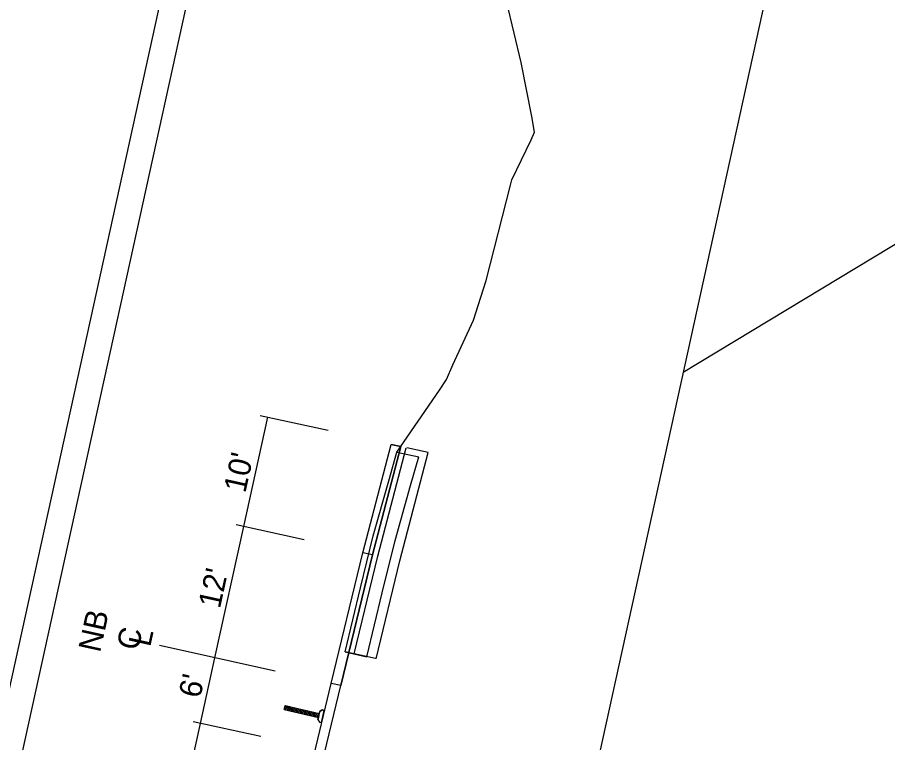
# Model space of a CAD drawing. Extents: x 14104283 to 14121738, y 8635219 to 8671666.
# Drawn here: x 14107408.8 to 14107719.8, y 8639476.7 to 8639735.9 of the extents above; entities that cross this region are included whole.
import ezdxf

# ---------------------------------------------------------------- set-up
doc = ezdxf.new("R2010")
doc.units = 0
for name, color, linetype in [('Cell', 7, 'Continuous'), ('dsnNonPlotable', 7, 'Continuous'), ('dsnShadingPaved', 7, 'Continuous'), ('dsnTextFinalPlan', 7, 'Continuous'), ('dsnTextOverlapEven', 7, 'Continuous'), ('TC_ShoulderPCC', 7, 'Continuous'), ('TC_Subbase', 7, 'Continuous'), ('TC_SubgradeTreatment', 7, 'Continuous'), ('TC_SubstrataExistingPavement', 7, 'Continuous'), ('Terrain', 7, 'Continuous')]:
    doc.layers.add(name, color=color, linetype=linetype)

msp = doc.modelspace()

# ---------------------------------------------------------------- linework, layer by layer
at = {"layer": 'Cell'}
for p, q in [((14107504.17, 8639488.53), (14107504.51, 8639489.98)), ((14107504.51, 8639489.98), (14107516.71, 8639487.11)), ((14107505.67, 8639488.18), (14107504.57, 8639489.96)), ((14107506.44, 8639488), (14107505.34, 8639489.78)), ((14107504.17, 8639488.53), (14107516.37, 8639485.66)), ((14107504.9, 8639488.36), (14107504.34, 8639489.26)), ((14107507.22, 8639487.82), (14107506.11, 8639489.6)), ((14107507.99, 8639487.63), (14107506.88, 8639489.42)), ((14107508.76, 8639487.45), (14107507.66, 8639489.24)), ((14107509.54, 8639487.27), (14107508.43, 8639489.06)), ((14107510.31, 8639487.09), (14107509.2, 8639488.87)), ((14107511.08, 8639486.91), (14107509.98, 8639488.69)), ((14107511.86, 8639486.72), (14107510.75, 8639488.51)), ((14107512.63, 8639486.54), (14107511.52, 8639488.33)), ((14107513.4, 8639486.36), (14107512.3, 8639488.15)), ((14107514.17, 8639486.18), (14107513.07, 8639487.97)), ((14107514.95, 8639486), (14107513.84, 8639487.78)), ((14107515.72, 8639485.82), (14107514.62, 8639487.6)), ((14107516.4, 8639485.79), (14107515.39, 8639487.42)), ((14107516.58, 8639486.56), (14107516.16, 8639487.24)), ((14107516.2, 8639484.94), (14107516.88, 8639487.83)), ((14107516.71, 8639487.11), (14107516.37, 8639485.66)), ((14107516.88, 8639487.83), (14107516.71, 8639487.11)), ((14107517.76, 8639488.39), (14107516.88, 8639487.83)), ((14107516.88, 8639487.83), (14107517.76, 8639488.39)), ((14107517.46, 8639483.88), (14107518.48, 8639488.22)), ((14107517.46, 8639483.88), (14107518.48, 8639488.22)), ((14107518.48, 8639488.22), (14107517.76, 8639488.39)), ((14107517.76, 8639488.39), (14107518.48, 8639488.22)), ((14107516.37, 8639485.66), (14107516.2, 8639484.94)), ((14107516.2, 8639484.94), (14107516.74, 8639484.05)), ((14107516.2, 8639484.94), (14107516.74, 8639484.05)), ((14107516.74, 8639484.05), (14107517.46, 8639483.88)), ((14107516.74, 8639484.05), (14107517.46, 8639483.88))]:
    msp.add_line(p, q, dxfattribs=at)
at = {"layer": 'dsnNonPlotable'}
msp.add_lwpolyline([(14107218.44, 8638642.33), (14107554.83, 8640173.31), (14108541.3, 8639956.56), (14108204.91, 8638425.58)], close=True, dxfattribs=at)
at = {"layer": 'dsnShadingPaved'}
msp.add_lwpolyline([(14107520.99, 8639497.88), (14107532.24, 8639544.57), (14107542.4, 8639583.28), (14107545.82, 8639582.53), (14107535.66, 8639543.8), (14107524.41, 8639497.13)], close=True, dxfattribs=at)
at = {"layer": 'dsnTextFinalPlan'}
for p, q in [((14107489.71, 8639553.9), (14107498.29, 8639592.97)), ((14107519.84, 8639588.23), (14107495.62, 8639593.56)), ((14107479.41, 8639507.02), (14107489.71, 8639553.9)), ((14107511.26, 8639549.17), (14107487.04, 8639554.49)), ((14107500.96, 8639502.28), (14107459.63, 8639511.37)), ((14107474.26, 8639483.58), (14107479.41, 8639507.02)), ((14107463.96, 8639436.7), (14107474.26, 8639483.58)), ((14107495.81, 8639478.84), (14107471.59, 8639484.16))]:
    msp.add_line(p, q, dxfattribs=at)
msp.add_lwpolyline([(14107277.52, 8638867.57), (14107491.18, 8639840), (14107687.99, 8639796.76), (14107474.33, 8638824.33)], close=True, dxfattribs=at)
at = {"layer": 'dsnTextOverlapEven'}
msp.add_lwpolyline([(14107277.52, 8638867.57), (14107491.18, 8639840), (14107687.99, 8639796.76), (14107474.33, 8638824.33)], close=True, dxfattribs=at)
at = {"layer": 'TC_ShoulderPCC'}
for p, q in [((14107795.79, 8639699.23), (14107646.73, 8639608.96)), ((14107532.24, 8639544.57), (14107542.4, 8639583.28)), ((14107545.82, 8639582.53), (14107542.4, 8639583.28)), ((14107535.66, 8639543.8), (14107545.82, 8639582.53)), ((14107520.99, 8639497.88), (14107532.24, 8639544.57)), ((14107524.41, 8639497.13), (14107535.66, 8639543.8)), ((14107535.66, 8639543.82), (14107532.24, 8639544.57)), ((14107524.41, 8639497.13), (14107520.99, 8639497.88))]:
    msp.add_line(p, q, dxfattribs=at)
at = {"layer": 'TC_Subbase'}
for p, q in [((14107537.61, 8639543.38), (14107547.78, 8639582.1)), ((14107529.18, 8639508.37), (14107537.61, 8639543.38)), ((14107524.41, 8639497.13), (14107527.22, 8639508.8)), ((14107529.18, 8639508.37), (14107525.89, 8639509.09))]:
    msp.add_line(p, q, dxfattribs=at)
at = {"layer": 'TC_SubgradeTreatment'}
for p, q in [((14107545.43, 8639541.66), (14107555.59, 8639580.38)), ((14107555.59, 8639580.38), (14107548.01, 8639582.04)), ((14107536.99, 8639506.65), (14107545.43, 8639541.66)), ((14107536.75, 8639506.71), (14107529.18, 8639508.37))]:
    msp.add_line(p, q, dxfattribs=at)
at = {"layer": 'TC_SubstrataExistingPavement'}
for p, q in [((14107544.43, 8639580.51), (14107552.24, 8639578.79)), ((14107525.89, 8639509.09), (14107533.7, 8639507.38)), ((14107513.16, 8639450.46), (14107524.41, 8639497.13))]:
    msp.add_line(p, q, dxfattribs=at)
msp.add_lwpolyline([(14107533.7, 8639507.38), (14107539.21, 8639530.27), (14107543.78, 8639548.94), (14107549.33, 8639568.6), (14107552.24, 8639578.79)], dxfattribs=at)
at = {"layer": 'Terrain'}
msp.add_line((14107509.74, 8639451.2), (14107520.99, 8639497.88), dxfattribs=at)
msp.add_lwpolyline([(14107525.89, 8639509.09), (14107531.4, 8639531.98), (14107535.97, 8639550.66), (14107541.52, 8639570.32), (14107544.43, 8639580.51), (14107559.65, 8639602.7), (14107562.12, 8639606.47), (14107564.43, 8639611.69), (14107571.86, 8639627.66), (14107574.46, 8639635.96), (14107576.29, 8639641.83), (14107585.05, 8639676), (14107585.49, 8639677.86), (14107592.37, 8639692.22), (14107593.58, 8639694.92), (14107592.61, 8639700.55), (14107588.88, 8639719.85), (14107586.35, 8639730.25), (14107583.54, 8639741.75), (14107585.05, 8639748.4), (14107585.92, 8639751.95), (14107585.4, 8639755.02), (14107583.61, 8639766.37), (14107584.86, 8639771.8)], dxfattribs=at)

# ---------------------------------------------------------------- texts
at = {"layer": 'dsnTextFinalPlan'}
for s, p in [("10'", (14107490.26, 8639565.65)), ("12'", (14107481.18, 8639524.32)), ('NB', (14107438.35, 8639508.62)), ('C', (14107452, 8639509.33)), ('L', (14107456.26, 8639510.64)), ("6'", (14107474.14, 8639492.29))]:
    msp.add_text(s, height=8, rotation=77.6078, dxfattribs=at).set_placement(p)

doc.saveas('drawing.dxf')
